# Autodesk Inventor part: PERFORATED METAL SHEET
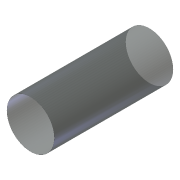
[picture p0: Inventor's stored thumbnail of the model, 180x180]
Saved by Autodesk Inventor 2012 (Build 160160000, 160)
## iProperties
Created: 2011-05
Part Number: PERFORATED METAL SHEET
Material: Stainless Steel, 440C
Document SubType Name: Modeling
Designer: Dimitris
Mass: 9714.59 g
Surface Area: 25095 cm^2
Volume: 1253.5 cm^3
Density: 7.75 g/cm^3
Author: Dimitris
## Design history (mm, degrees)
sketch "Sketch1"
  geometry: C1 r 200 at (0, 0); C2 r 199 at (0, 0); 1 further point
  constraints: 2 centre point, 1 coincident
  dimensions: "OD" = 400 diameter of C1; "d1" = 1 radial gap between concentric circles of C1 C2
extrude "Extrusion1" new body sketch "Sketch1" taper "d3" = 0 deg; stored distance "Length" = 1000
body "Solid1"
